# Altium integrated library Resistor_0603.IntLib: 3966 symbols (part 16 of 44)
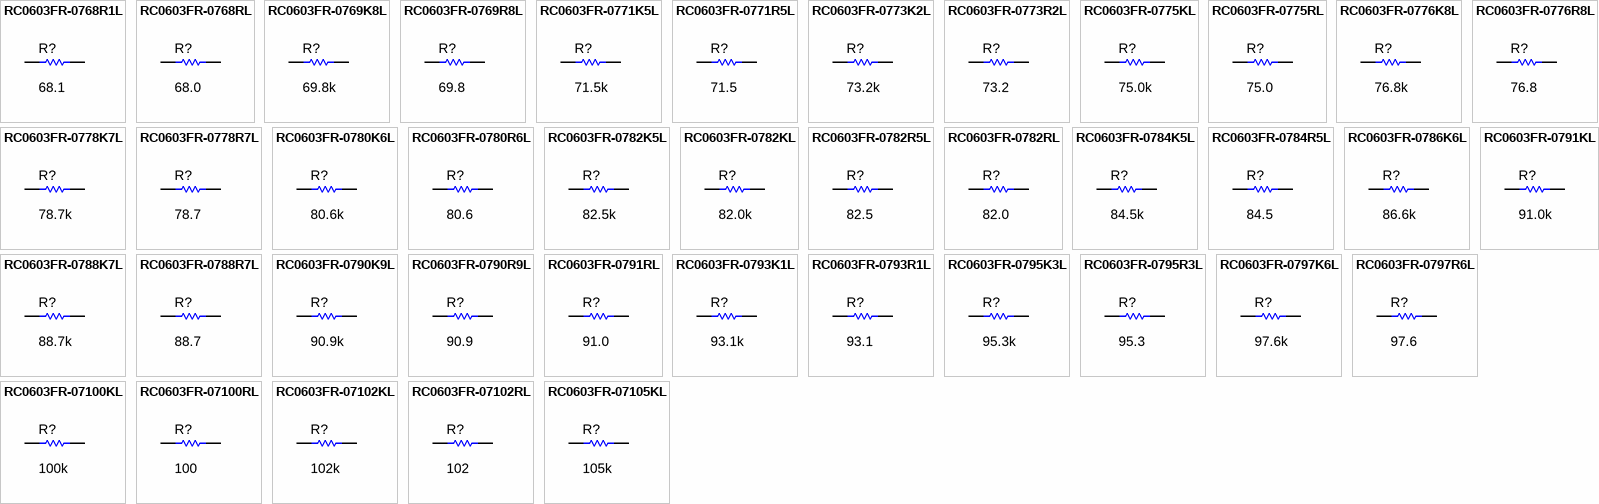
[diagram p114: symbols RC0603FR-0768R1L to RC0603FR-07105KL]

## RC0603FR-0790R9L
designator R?  ValueDisplayed: 90.9  (hidden comment: RC0603FR-0790R9L)
RES, 90.9, 1%, 0.1 W, 0603; Manufacturer: Yageo America; CompType: Resistor; Value: 90.9; Value_Code: 90R9; Tolerance_%: 1; Power_W: 0.1; Value2: 0.1W; VDC_V: 150; TempCo: 200 ppm/C; SizeArea_mm2: 1.28; SizeX_mm: 1.6; SizeY_mm: 0.8; EIA_Code: E96; U/M: EA; AEC Category: Q200
signal-integrity model Resistor
simulation model Resistor
footprint 0603
footprint 0603M
footprint 0603L
footprint 0603_HV
footprint 0603S
pins: 1, 2

## RC0603FR-0791KL
designator R?  ValueDisplayed: 91.0k  (hidden comment: RC0603FR-0791KL)
RES, 91.0 k, 1%, 0.1 W, 0603; Manufacturer: Yageo America; CompType: Resistor; Value: 91.0k; Res_ohm: 91000; Value_Code: 91k0; Tolerance_%: 1; Power_W: 0.1; Value2: 0.1W; VDC_V: 150; TempCo: 200 ppm/C; SizeArea_mm2: 1.28; SizeX_mm: 1.6; SizeY_mm: 0.8; U/M: EA; AEC Category: Q200
signal-integrity model Resistor
simulation model Resistor
footprint 0603
footprint 0603M
footprint 0603L
footprint 0603_HV
footprint 0603S
pins: 1, 2

## RC0603FR-0791RL
designator R?  ValueDisplayed: 91.0  (hidden comment: RC0603FR-0791RL)
RES, 91.0, 1%, 0.1 W, 0603; Manufacturer: Yageo America; CompType: Resistor; Value: 91.0; Res_ohm: 91; Value_Code: 91R0; Tolerance_%: 1; Power_W: 0.1; Value2: 0.1W; VDC_V: 150; TempCo: 200 ppm/C; SizeArea_mm2: 1.28; SizeX_mm: 1.6; SizeY_mm: 0.8; U/M: EA; AEC Category: Q200
signal-integrity model Resistor
simulation model Resistor
footprint 0603
footprint 0603M
footprint 0603L
footprint 0603_HV
footprint 0603S
pins: 1, 2

## RC0603FR-0793K1L
designator R?  ValueDisplayed: 93.1k  (hidden comment: RC0603FR-0793K1L)
RES, 93.1 k, 1%, 0.1 W, 0603; Manufacturer: Yageo America; CompType: Resistor; Value: 93.1k; Res_ohm: 93100; Value_Code: 93k1; Tolerance_%: 1; Power_W: 0.1; Value2: 0.1W; VDC_V: 150; TempCo: 200 ppm/C; SizeArea_mm2: 1.28; SizeX_mm: 1.6; SizeY_mm: 0.8; EIA_Code: E96; U/M: EA; AEC Category: Q200; Green_Lifecycle: Active; Green_REACh: Passed
signal-integrity model Resistor
simulation model Resistor
footprint 0603
footprint 0603M
footprint 0603L
footprint 0603_HV
footprint 0603S
pins: 1, 2

## RC0603FR-0793R1L
designator R?  ValueDisplayed: 93.1  (hidden comment: RC0603FR-0793R1L)
RES, 93.1, 1%, 0.1 W, 0603; Manufacturer: Yageo America; CompType: Resistor; Value: 93.1; Value_Code: 93R1; Tolerance_%: 1; Power_W: 0.1; Value2: 0.1W; VDC_V: 150; TempCo: 200 ppm/C; SizeArea_mm2: 1.28; SizeX_mm: 1.6; SizeY_mm: 0.8; EIA_Code: E96; U/M: EA; AEC Category: Q200
signal-integrity model Resistor
simulation model Resistor
footprint 0603
footprint 0603M
footprint 0603L
footprint 0603_HV
footprint 0603S
pins: 1, 2

## RC0603FR-0795K3L
designator R?  ValueDisplayed: 95.3k  (hidden comment: RC0603FR-0795K3L)
RES, 95.3 k, 1%, 0.1 W, 0603; Manufacturer: Yageo America; CompType: Resistor; Value: 95.3k; Res_ohm: 95300; Value_Code: 95k3; Tolerance_%: 1; Power_W: 0.1; Value2: 0.1W; VDC_V: 150; TempCo: 200 ppm/C; SizeArea_mm2: 1.28; SizeX_mm: 1.6; SizeY_mm: 0.8; EIA_Code: E96; U/M: EA; AEC Category: Q200; Green_Lifecycle: Active; Green_REACh: Passed
signal-integrity model Resistor
simulation model Resistor
footprint 0603
footprint 0603M
footprint 0603L
footprint 0603_HV
footprint 0603S
pins: 1, 2

## RC0603FR-0795R3L
designator R?  ValueDisplayed: 95.3  (hidden comment: RC0603FR-0795R3L)
RES, 95.3, 1%, 0.1 W, 0603; Manufacturer: Yageo America; CompType: Resistor; Value: 95.3; Value_Code: 95R3; Tolerance_%: 1; Power_W: 0.1; Value2: 0.1W; VDC_V: 150; TempCo: 200 ppm/C; SizeArea_mm2: 1.28; SizeX_mm: 1.6; SizeY_mm: 0.8; EIA_Code: E96; U/M: EA; AEC Category: Q200
signal-integrity model Resistor
simulation model Resistor
footprint 0603
footprint 0603M
footprint 0603L
footprint 0603_HV
footprint 0603S
pins: 1, 2

## RC0603FR-0797K6L
designator R?  ValueDisplayed: 97.6k  (hidden comment: RC0603FR-0797K6L)
RES, 97.6 k, 1%, 0.1 W, 0603; Manufacturer: Yageo America; CompType: Resistor; Value: 97.6k; Res_ohm: 97600; Value_Code: 97k6; Tolerance_%: 1; Power_W: 0.1; Value2: 0.1W; VDC_V: 150; TempCo: 200 ppm/C; SizeArea_mm2: 1.28; SizeX_mm: 1.6; SizeY_mm: 0.8; EIA_Code: E96; U/M: EA; AEC Category: Q200
signal-integrity model Resistor
simulation model Resistor
footprint 0603
footprint 0603M
footprint 0603L
footprint 0603_HV
footprint 0603S
pins: 1, 2

## RC0603FR-0797R6L
designator R?  ValueDisplayed: 97.6  (hidden comment: RC0603FR-0797R6L)
RES, 97.6, 1%, 0.1 W, 0603; Manufacturer: Yageo America; CompType: Resistor; Value: 97.6; Value_Code: 97R6; Tolerance_%: 1; Power_W: 0.1; Value2: 0.1W; VDC_V: 150; TempCo: 200 ppm/C; SizeArea_mm2: 1.28; SizeX_mm: 1.6; SizeY_mm: 0.8; EIA_Code: E96; U/M: EA; AEC Category: Q200
signal-integrity model Resistor
simulation model Resistor
footprint 0603
footprint 0603M
footprint 0603L
footprint 0603_HV
footprint 0603S
pins: 1, 2

## RC0603FR-07100KL
designator R?  ValueDisplayed: 100k  (hidden comment: RC0603FR-07100KL)
RES, 100 k, 1%, 0.1 W, 0603; Manufacturer: Yageo America; CompType: Resistor; Value: 100k; Res_ohm: 100000; Tolerance_%: 1; Power_W: 0.1; Value2: 0.1W; VDC_V: 150; TempCo: 200 ppm/C; SizeArea_mm2: 1.28; SizeX_mm: 1.6; SizeY_mm: 0.8; EIA_Code: E96; U/M: EA; AEC Category: Q200; Green_Lifecycle: Active; Green_REACh: Passed
signal-integrity model Resistor
simulation model Resistor
footprint 0603
footprint 0603M
footprint 0603L
footprint 0603_HV
footprint 0603S
pins: 1, 2

## RC0603FR-07100RL
designator R?  ValueDisplayed: 100  (hidden comment: RC0603FR-07100RL)
RES, 100, 1%, 0.1 W, 0603; Manufacturer: Yageo America; CompType: Resistor; Value: 100; Value_Code: 100R; Tolerance_%: 1; Power_W: 0.1; Value2: 0.1W; VDC_V: 150; TempCo: 200 ppm/C; SizeArea_mm2: 1.28; SizeX_mm: 1.6; SizeY_mm: 0.8; EIA_Code: E96; U/M: EA; AEC Category: Q200; Green_Lifecycle: Active; Green_REACh: Passed
signal-integrity model Resistor
simulation model Resistor
footprint 0603
footprint 0603M
footprint 0603L
footprint 0603_HV
footprint 0603S
pins: 1, 2

## RC0603FR-07102KL
designator R?  ValueDisplayed: 102k  (hidden comment: RC0603FR-07102KL)
RES, 102 k, 1%, 0.1 W, 0603; Manufacturer: Yageo America; CompType: Resistor; Value: 102k; Res_ohm: 102000; Tolerance_%: 1; Power_W: 0.1; Value2: 0.1W; VDC_V: 150; TempCo: 200 ppm/C; SizeArea_mm2: 1.28; SizeX_mm: 1.6; SizeY_mm: 0.8; EIA_Code: E96; U/M: EA; AEC Category: Q200; Green_Lifecycle: Active; Green_REACh: Passed
signal-integrity model Resistor
simulation model Resistor
footprint 0603
footprint 0603M
footprint 0603L
footprint 0603_HV
footprint 0603S
pins: 1, 2

## RC0603FR-07102RL
designator R?  ValueDisplayed: 102  (hidden comment: RC0603FR-07102RL)
RES, 102, 1%, 0.1 W, 0603; Manufacturer: Yageo America; CompType: Resistor; Value: 102; Value_Code: 102R; Tolerance_%: 1; Power_W: 0.1; Value2: 0.1W; VDC_V: 150; TempCo: 200 ppm/C; SizeArea_mm2: 1.28; SizeX_mm: 1.6; SizeY_mm: 0.8; EIA_Code: E96; U/M: EA; AEC Category: Q200
signal-integrity model Resistor
simulation model Resistor
footprint 0603
footprint 0603M
footprint 0603L
footprint 0603_HV
footprint 0603S
pins: 1, 2

## RC0603FR-07105KL
designator R?  ValueDisplayed: 105k  (hidden comment: RC0603FR-07105KL)
RES, 105 k, 1%, 0.1 W, 0603; Manufacturer: Yageo America; CompType: Resistor; Value: 105k; Res_ohm: 105000; Tolerance_%: 1; Power_W: 0.1; Value2: 0.1W; VDC_V: 150; TempCo: 200 ppm/C; SizeArea_mm2: 1.28; SizeX_mm: 1.6; SizeY_mm: 0.8; EIA_Code: E96; U/M: EA; AEC Category: Q200
signal-integrity model Resistor
simulation model Resistor
footprint 0603
footprint 0603M
footprint 0603L
footprint 0603_HV
footprint 0603S
pins: 1, 2

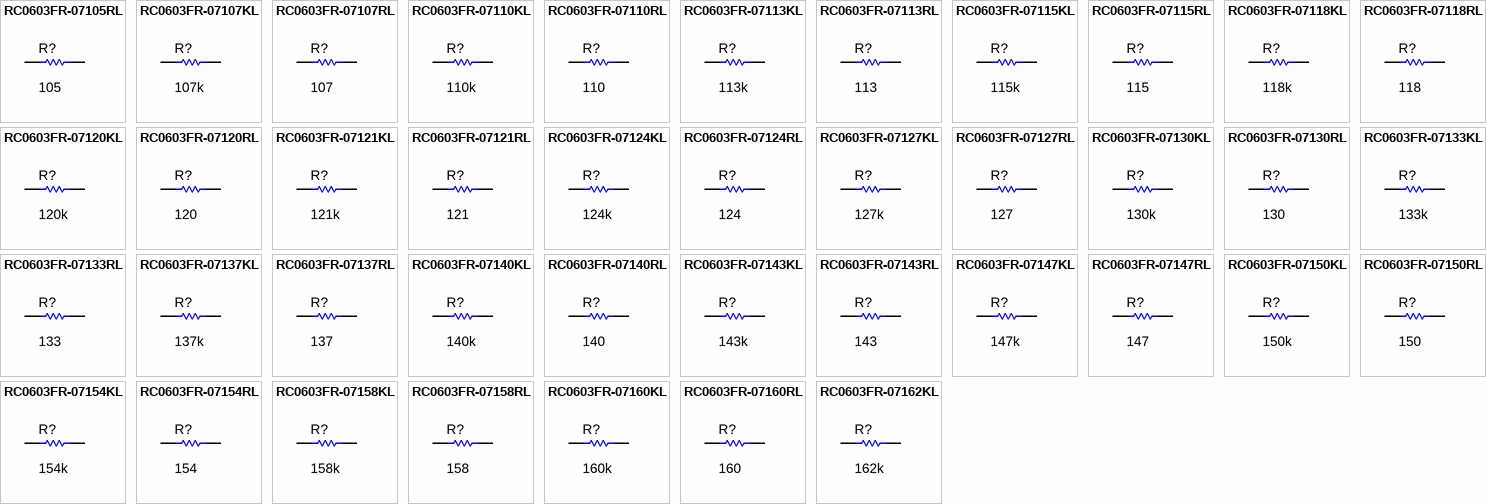
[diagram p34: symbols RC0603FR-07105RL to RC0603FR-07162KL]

## RC0603FR-07105RL
designator R?  ValueDisplayed: 105  (hidden comment: RC0603FR-07105RL)
RES, 105, 1%, 0.1 W, 0603; Manufacturer: Yageo America; CompType: Resistor; Value: 105; Value_Code: 105R; Tolerance_%: 1; Power_W: 0.1; Value2: 0.1W; VDC_V: 150; TempCo: 200 ppm/C; SizeArea_mm2: 1.28; SizeX_mm: 1.6; SizeY_mm: 0.8; EIA_Code: E96; U/M: EA; AEC Category: Q200
signal-integrity model Resistor
simulation model Resistor
footprint 0603
footprint 0603M
footprint 0603L
footprint 0603_HV
footprint 0603S
pins: 1, 2

## RC0603FR-07107KL
designator R?  ValueDisplayed: 107k  (hidden comment: RC0603FR-07107KL)
RES, 107 k, 1%, 0.1 W, 0603; Manufacturer: Yageo America; CompType: Resistor; Value: 107k; Res_ohm: 107000; Tolerance_%: 1; Power_W: 0.1; Value2: 0.1W; VDC_V: 150; TempCo: 200 ppm/C; SizeArea_mm2: 1.28; SizeX_mm: 1.6; SizeY_mm: 0.8; EIA_Code: E96; U/M: EA; AEC Category: Q200; Green_Lifecycle: Active; Green_REACh: Passed
signal-integrity model Resistor
simulation model Resistor
footprint 0603
footprint 0603M
footprint 0603L
footprint 0603_HV
footprint 0603S
pins: 1, 2

## RC0603FR-07107RL
designator R?  ValueDisplayed: 107  (hidden comment: RC0603FR-07107RL)
RES, 107, 1%, 0.1 W, 0603; Manufacturer: Yageo America; CompType: Resistor; Value: 107; Value_Code: 107R; Tolerance_%: 1; Power_W: 0.1; Value2: 0.1W; VDC_V: 150; TempCo: 200 ppm/C; SizeArea_mm2: 1.28; SizeX_mm: 1.6; SizeY_mm: 0.8; EIA_Code: E96; U/M: EA; AEC Category: Q200
signal-integrity model Resistor
simulation model Resistor
footprint 0603
footprint 0603M
footprint 0603L
footprint 0603_HV
footprint 0603S
pins: 1, 2

## RC0603FR-07110KL
designator R?  ValueDisplayed: 110k  (hidden comment: RC0603FR-07110KL)
RES, 110 k, 1%, 0.1 W, 0603; Manufacturer: Yageo America; CompType: Resistor; Value: 110k; Res_ohm: 110000; Tolerance_%: 1; Power_W: 0.1; Value2: 0.1W; VDC_V: 150; TempCo: 200 ppm/C; SizeArea_mm2: 1.28; SizeX_mm: 1.6; SizeY_mm: 0.8; EIA_Code: E96; U/M: EA; AEC Category: Q200
signal-integrity model Resistor
simulation model Resistor
footprint 0603
footprint 0603M
footprint 0603L
footprint 0603_HV
footprint 0603S
pins: 1, 2

## RC0603FR-07110RL
designator R?  ValueDisplayed: 110  (hidden comment: RC0603FR-07110RL)
RES, 110, 1%, 0.1 W, 0603; Manufacturer: Yageo America; CompType: Resistor; Value: 110; Value_Code: 110R; Tolerance_%: 1; Power_W: 0.1; Value2: 0.1W; VDC_V: 150; TempCo: 200 ppm/C; SizeArea_mm2: 1.28; SizeX_mm: 1.6; SizeY_mm: 0.8; EIA_Code: E96; U/M: EA; AEC Category: Q200
signal-integrity model Resistor
simulation model Resistor
footprint 0603
footprint 0603M
footprint 0603L
footprint 0603_HV
footprint 0603S
pins: 1, 2

## RC0603FR-07113KL
designator R?  ValueDisplayed: 113k  (hidden comment: RC0603FR-07113KL)
RES, 113 k, 1%, 0.1 W, 0603; Manufacturer: Yageo America; CompType: Resistor; Value: 113k; Res_ohm: 113000; Tolerance_%: 1; Power_W: 0.1; Value2: 0.1W; VDC_V: 150; TempCo: 200 ppm/C; SizeArea_mm2: 1.28; SizeX_mm: 1.6; SizeY_mm: 0.8; EIA_Code: E96; U/M: EA; AEC Category: Q200
signal-integrity model Resistor
simulation model Resistor
footprint 0603
footprint 0603M
footprint 0603L
footprint 0603_HV
footprint 0603S
pins: 1, 2

## RC0603FR-07113RL
designator R?  ValueDisplayed: 113  (hidden comment: RC0603FR-07113RL)
RES, 113, 1%, 0.1 W, 0603; Manufacturer: Yageo America; CompType: Resistor; Value: 113; Value_Code: 113R; Tolerance_%: 1; Power_W: 0.1; Value2: 0.1W; VDC_V: 150; TempCo: 200 ppm/C; SizeArea_mm2: 1.28; SizeX_mm: 1.6; SizeY_mm: 0.8; EIA_Code: E96; U/M: EA; AEC Category: Q200
signal-integrity model Resistor
simulation model Resistor
footprint 0603
footprint 0603M
footprint 0603L
footprint 0603_HV
footprint 0603S
pins: 1, 2

## RC0603FR-07115KL
designator R?  ValueDisplayed: 115k  (hidden comment: RC0603FR-07115KL)
RES, 115 k, 1%, 0.1 W, 0603; Manufacturer: Yageo America; CompType: Resistor; Value: 115k; Res_ohm: 115000; Tolerance_%: 1; Power_W: 0.1; Value2: 0.1W; VDC_V: 150; TempCo: 200 ppm/C; SizeArea_mm2: 1.28; SizeX_mm: 1.6; SizeY_mm: 0.8; EIA_Code: E96; U/M: EA; AEC Category: Q200
signal-integrity model Resistor
simulation model Resistor
footprint 0603
footprint 0603M
footprint 0603L
footprint 0603_HV
footprint 0603S
pins: 1, 2

## RC0603FR-07115RL
designator R?  ValueDisplayed: 115  (hidden comment: RC0603FR-07115RL)
RES, 115, 1%, 0.1 W, 0603; Manufacturer: Yageo America; CompType: Resistor; Value: 115; Value_Code: 115R; Tolerance_%: 1; Power_W: 0.1; Value2: 0.1W; VDC_V: 150; TempCo: 200 ppm/C; SizeArea_mm2: 1.28; SizeX_mm: 1.6; SizeY_mm: 0.8; EIA_Code: E96; U/M: EA; AEC Category: Q200
signal-integrity model Resistor
simulation model Resistor
footprint 0603
footprint 0603M
footprint 0603L
footprint 0603_HV
footprint 0603S
pins: 1, 2

## RC0603FR-07118KL
designator R?  ValueDisplayed: 118k  (hidden comment: RC0603FR-07118KL)
RES, 118 k, 1%, 0.1 W, 0603; Manufacturer: Yageo America; CompType: Resistor; Value: 118k; Res_ohm: 118000; Tolerance_%: 1; Power_W: 0.1; Value2: 0.1W; VDC_V: 150; TempCo: 200 ppm/C; SizeArea_mm2: 1.28; SizeX_mm: 1.6; SizeY_mm: 0.8; EIA_Code: E96; U/M: EA; AEC Category: Q200; Green_Lifecycle: Active; Green_REACh: Passed
signal-integrity model Resistor
simulation model Resistor
footprint 0603
footprint 0603M
footprint 0603L
footprint 0603_HV
footprint 0603S
pins: 1, 2

## RC0603FR-07118RL
designator R?  ValueDisplayed: 118  (hidden comment: RC0603FR-07118RL)
RES, 118, 1%, 0.1 W, 0603; Manufacturer: Yageo America; CompType: Resistor; Value: 118; Value_Code: 118R; Tolerance_%: 1; Power_W: 0.1; Value2: 0.1W; VDC_V: 150; TempCo: 200 ppm/C; SizeArea_mm2: 1.28; SizeX_mm: 1.6; SizeY_mm: 0.8; EIA_Code: E96; U/M: EA; AEC Category: Q200
signal-integrity model Resistor
simulation model Resistor
footprint 0603
footprint 0603M
footprint 0603L
footprint 0603_HV
footprint 0603S
pins: 1, 2

## RC0603FR-07120KL
designator R?  ValueDisplayed: 120k  (hidden comment: RC0603FR-07120KL)
RES, 120 k, 1%, 0.1 W, 0603; Manufacturer: Yageo America; CompType: Resistor; Value: 120k; Res_ohm: 120000; Tolerance_%: 1; Power_W: 0.1; Value2: 0.1W; VDC_V: 150; TempCo: 200 ppm/C; SizeArea_mm2: 1.28; SizeX_mm: 1.6; SizeY_mm: 0.8; U/M: EA; AEC Category: Q200
signal-integrity model Resistor
simulation model Resistor
footprint 0603
footprint 0603M
footprint 0603L
footprint 0603_HV
footprint 0603S
pins: 1, 2

## RC0603FR-07120RL
designator R?  ValueDisplayed: 120  (hidden comment: RC0603FR-07120RL)
RES, 120, 1%, 0.1 W, 0603; Manufacturer: Yageo America; CompType: Resistor; Value: 120; Value_Code: 120R; Tolerance_%: 1; Power_W: 0.1; Value2: 0.1W; VDC_V: 150; TempCo: 200 ppm/C; SizeArea_mm2: 1.28; SizeX_mm: 1.6; SizeY_mm: 0.8; U/M: EA; AEC Category: Q200; Green_Lifecycle: Active; Green_REACh: Passed
signal-integrity model Resistor
simulation model Resistor
footprint 0603
footprint 0603M
footprint 0603L
footprint 0603_HV
footprint 0603S
pins: 1, 2

## RC0603FR-07121KL
designator R?  ValueDisplayed: 121k  (hidden comment: RC0603FR-07121KL)
RES, 121 k, 1%, 0.1 W, 0603; Manufacturer: Yageo America; CompType: Resistor; Value: 121k; Res_ohm: 121000; Tolerance_%: 1; Power_W: 0.1; Value2: 0.1W; VDC_V: 150; TempCo: 200 ppm/C; SizeArea_mm2: 1.28; SizeX_mm: 1.6; SizeY_mm: 0.8; EIA_Code: E96; U/M: EA; AEC Category: Q200; Green_Lifecycle: Active; Green_REACh: Passed
signal-integrity model Resistor
simulation model Resistor
footprint 0603
footprint 0603M
footprint 0603L
footprint 0603_HV
footprint 0603S
pins: 1, 2

## RC0603FR-07121RL
designator R?  ValueDisplayed: 121  (hidden comment: RC0603FR-07121RL)
RES, 121, 1%, 0.1 W, 0603; Manufacturer: Yageo America; CompType: Resistor; Value: 121; Value_Code: 121R; Tolerance_%: 1; Power_W: 0.1; Value2: 0.1W; VDC_V: 150; TempCo: 200 ppm/C; SizeArea_mm2: 1.28; SizeX_mm: 1.6; SizeY_mm: 0.8; EIA_Code: E96; U/M: EA; AEC Category: Q200
signal-integrity model Resistor
simulation model Resistor
footprint 0603
footprint 0603M
footprint 0603L
footprint 0603_HV
footprint 0603S
pins: 1, 2

## RC0603FR-07124KL
designator R?  ValueDisplayed: 124k  (hidden comment: RC0603FR-07124KL)
RES, 124 k, 1%, 0.1 W, 0603; Manufacturer: Yageo America; CompType: Resistor; Value: 124k; Res_ohm: 124000; Tolerance_%: 1; Power_W: 0.1; Value2: 0.1W; VDC_V: 150; TempCo: 200 ppm/C; SizeArea_mm2: 1.28; SizeX_mm: 1.6; SizeY_mm: 0.8; EIA_Code: E96; U/M: EA; AEC Category: Q200; Green_Lifecycle: Active; Green_REACh: Passed
signal-integrity model Resistor
simulation model Resistor
footprint 0603
footprint 0603M
footprint 0603L
footprint 0603_HV
footprint 0603S
pins: 1, 2

## RC0603FR-07124RL
designator R?  ValueDisplayed: 124  (hidden comment: RC0603FR-07124RL)
RES, 124, 1%, 0.1 W, 0603; Manufacturer: Yageo America; CompType: Resistor; Value: 124; Value_Code: 124R; Tolerance_%: 1; Power_W: 0.1; Value2: 0.1W; VDC_V: 150; TempCo: 200 ppm/C; SizeArea_mm2: 1.28; SizeX_mm: 1.6; SizeY_mm: 0.8; EIA_Code: E96; U/M: EA; AEC Category: Q200
signal-integrity model Resistor
simulation model Resistor
footprint 0603
footprint 0603M
footprint 0603L
footprint 0603_HV
footprint 0603S
pins: 1, 2

## RC0603FR-07127KL
designator R?  ValueDisplayed: 127k  (hidden comment: RC0603FR-07127KL)
RES, 127 k, 1%, 0.1 W, 0603; Manufacturer: Yageo America; CompType: Resistor; Value: 127k; Res_ohm: 127000; Tolerance_%: 1; Power_W: 0.1; Value2: 0.1W; VDC_V: 150; TempCo: 200 ppm/C; SizeArea_mm2: 1.28; SizeX_mm: 1.6; SizeY_mm: 0.8; EIA_Code: E96; U/M: EA; AEC Category: Q200; Green_Lifecycle: Active; Green_REACh: Passed
signal-integrity model Resistor
simulation model Resistor
footprint 0603
footprint 0603M
footprint 0603L
footprint 0603_HV
footprint 0603S
pins: 1, 2

## RC0603FR-07127RL
designator R?  ValueDisplayed: 127  (hidden comment: RC0603FR-07127RL)
RES, 127, 1%, 0.1 W, 0603; Manufacturer: Yageo America; CompType: Resistor; Value: 127; Value_Code: 127R; Tolerance_%: 1; Power_W: 0.1; Value2: 0.1W; VDC_V: 150; TempCo: 200 ppm/C; SizeArea_mm2: 1.28; SizeX_mm: 1.6; SizeY_mm: 0.8; EIA_Code: E96; U/M: EA; AEC Category: Q200
signal-integrity model Resistor
simulation model Resistor
footprint 0603
footprint 0603M
footprint 0603L
footprint 0603_HV
footprint 0603S
pins: 1, 2

## RC0603FR-07130KL
designator R?  ValueDisplayed: 130k  (hidden comment: RC0603FR-07130KL)
RES, 130 k, 1%, 0.1 W, 0603; Manufacturer: Yageo America; CompType: Resistor; Value: 130k; Res_ohm: 130000; Tolerance_%: 1; Power_W: 0.1; Value2: 0.1W; VDC_V: 150; TempCo: 200 ppm/C; SizeArea_mm2: 1.28; SizeX_mm: 1.6; SizeY_mm: 0.8; EIA_Code: E96; U/M: EA; AEC Category: Q200
signal-integrity model Resistor
simulation model Resistor
footprint 0603
footprint 0603M
footprint 0603L
footprint 0603_HV
footprint 0603S
pins: 1, 2

## RC0603FR-07130RL
designator R?  ValueDisplayed: 130  (hidden comment: RC0603FR-07130RL)
RES, 130, 1%, 0.1 W, 0603; Manufacturer: Yageo America; CompType: Resistor; Value: 130; Value_Code: 130R; Tolerance_%: 1; Power_W: 0.1; Value2: 0.1W; VDC_V: 150; TempCo: 200 ppm/C; SizeArea_mm2: 1.28; SizeX_mm: 1.6; SizeY_mm: 0.8; EIA_Code: E96; U/M: EA; AEC Category: Q200; Green_Lifecycle: Active; Green_REACh: Passed
signal-integrity model Resistor
simulation model Resistor
footprint 0603
footprint 0603M
footprint 0603L
footprint 0603_HV
footprint 0603S
pins: 1, 2

## RC0603FR-07133KL
designator R?  ValueDisplayed: 133k  (hidden comment: RC0603FR-07133KL)
RES, 133 k, 1%, 0.1 W, 0603; Manufacturer: Yageo America; CompType: Resistor; Value: 133k; Res_ohm: 133000; Tolerance_%: 1; Power_W: 0.1; Value2: 0.1W; VDC_V: 150; TempCo: 200 ppm/C; SizeArea_mm2: 1.28; SizeX_mm: 1.6; SizeY_mm: 0.8; EIA_Code: E96; U/M: EA; AEC Category: Q200; Green_Lifecycle: Active; Green_REACh: Passed
signal-integrity model Resistor
simulation model Resistor
footprint 0603
footprint 0603M
footprint 0603L
footprint 0603_HV
footprint 0603S
pins: 1, 2

## RC0603FR-07133RL
designator R?  ValueDisplayed: 133  (hidden comment: RC0603FR-07133RL)
RES, 133, 1%, 0.1 W, 0603; Manufacturer: Yageo America; CompType: Resistor; Value: 133; Value_Code: 133R; Tolerance_%: 1; Power_W: 0.1; Value2: 0.1W; VDC_V: 150; TempCo: 200 ppm/C; SizeArea_mm2: 1.28; SizeX_mm: 1.6; SizeY_mm: 0.8; EIA_Code: E96; U/M: EA; AEC Category: Q200
signal-integrity model Resistor
simulation model Resistor
footprint 0603
footprint 0603M
footprint 0603L
footprint 0603_HV
footprint 0603S
pins: 1, 2

## RC0603FR-07137KL
designator R?  ValueDisplayed: 137k  (hidden comment: RC0603FR-07137KL)
RES, 137 k, 1%, 0.1 W, 0603; Manufacturer: Yageo America; CompType: Resistor; Value: 137k; Res_ohm: 137000; Tolerance_%: 1; Power_W: 0.1; Value2: 0.1W; VDC_V: 150; TempCo: 200 ppm/C; SizeArea_mm2: 1.28; SizeX_mm: 1.6; SizeY_mm: 0.8; EIA_Code: E96; U/M: EA; AEC Category: Q200
signal-integrity model Resistor
simulation model Resistor
footprint 0603
footprint 0603M
footprint 0603L
footprint 0603_HV
footprint 0603S
pins: 1, 2

## RC0603FR-07137RL
designator R?  ValueDisplayed: 137  (hidden comment: RC0603FR-07137RL)
RES, 137, 1%, 0.1 W, 0603; Manufacturer: Yageo America; CompType: Resistor; Value: 137; Value_Code: 137R; Tolerance_%: 1; Power_W: 0.1; Value2: 0.1W; VDC_V: 150; TempCo: 200 ppm/C; SizeArea_mm2: 1.28; SizeX_mm: 1.6; SizeY_mm: 0.8; EIA_Code: E96; U/M: EA; AEC Category: Q200
signal-integrity model Resistor
simulation model Resistor
footprint 0603
footprint 0603M
footprint 0603L
footprint 0603_HV
footprint 0603S
pins: 1, 2

## RC0603FR-07140KL
designator R?  ValueDisplayed: 140k  (hidden comment: RC0603FR-07140KL)
RES, 140 k, 1%, 0.1 W, 0603; Manufacturer: Yageo America; CompType: Resistor; Value: 140k; Res_ohm: 140000; Tolerance_%: 1; Power_W: 0.1; Value2: 0.1W; VDC_V: 150; TempCo: 200 ppm/C; SizeArea_mm2: 1.28; SizeX_mm: 1.6; SizeY_mm: 0.8; EIA_Code: E96; U/M: EA; AEC Category: Q200
signal-integrity model Resistor
simulation model Resistor
footprint 0603
footprint 0603M
footprint 0603L
footprint 0603_HV
footprint 0603S
pins: 1, 2

## RC0603FR-07140RL
designator R?  ValueDisplayed: 140  (hidden comment: RC0603FR-07140RL)
RES, 140, 1%, 0.1 W, 0603; Manufacturer: Yageo America; CompType: Resistor; Value: 140; Value_Code: 140R; Tolerance_%: 1; Power_W: 0.1; Value2: 0.1W; VDC_V: 150; TempCo: 200 ppm/C; SizeArea_mm2: 1.28; SizeX_mm: 1.6; SizeY_mm: 0.8; EIA_Code: E96; U/M: EA; AEC Category: Q200
signal-integrity model Resistor
simulation model Resistor
footprint 0603
footprint 0603M
footprint 0603L
footprint 0603_HV
footprint 0603S
pins: 1, 2

## RC0603FR-07143KL
designator R?  ValueDisplayed: 143k  (hidden comment: RC0603FR-07143KL)
RES, 143 k, 1%, 0.1 W, 0603; Manufacturer: Yageo America; CompType: Resistor; Value: 143k; Res_ohm: 143000; Tolerance_%: 1; Power_W: 0.1; Value2: 0.1W; VDC_V: 150; TempCo: 200 ppm/C; SizeArea_mm2: 1.28; SizeX_mm: 1.6; SizeY_mm: 0.8; EIA_Code: E96; U/M: EA; AEC Category: Q200; Green_Lifecycle: Active; Green_REACh: Passed
signal-integrity model Resistor
simulation model Resistor
footprint 0603
footprint 0603M
footprint 0603L
footprint 0603_HV
footprint 0603S
pins: 1, 2

## RC0603FR-07143RL
designator R?  ValueDisplayed: 143  (hidden comment: RC0603FR-07143RL)
RES, 143, 1%, 0.1 W, 0603; Manufacturer: Yageo America; CompType: Resistor; Value: 143; Value_Code: 143R; Tolerance_%: 1; Power_W: 0.1; Value2: 0.1W; VDC_V: 150; TempCo: 200 ppm/C; SizeArea_mm2: 1.28; SizeX_mm: 1.6; SizeY_mm: 0.8; EIA_Code: E96; U/M: EA; AEC Category: Q200
signal-integrity model Resistor
simulation model Resistor
footprint 0603
footprint 0603M
footprint 0603L
footprint 0603_HV
footprint 0603S
pins: 1, 2

## RC0603FR-07147KL
designator R?  ValueDisplayed: 147k  (hidden comment: RC0603FR-07147KL)
RES, 147 k, 1%, 0.1 W, 0603; Manufacturer: Yageo America; CompType: Resistor; Value: 147k; Res_ohm: 147000; Tolerance_%: 1; Power_W: 0.1; Value2: 0.1W; VDC_V: 150; TempCo: 200 ppm/C; SizeArea_mm2: 1.28; SizeX_mm: 1.6; SizeY_mm: 0.8; EIA_Code: E96; U/M: EA; AEC Category: Q200; Green_Lifecycle: Active; Green_REACh: Passed
signal-integrity model Resistor
simulation model Resistor
footprint 0603
footprint 0603M
footprint 0603L
footprint 0603_HV
footprint 0603S
pins: 1, 2

## RC0603FR-07147RL
designator R?  ValueDisplayed: 147  (hidden comment: RC0603FR-07147RL)
RES, 147, 1%, 0.1 W, 0603; Manufacturer: Yageo America; CompType: Resistor; Value: 147; Value_Code: 147R; Tolerance_%: 1; Power_W: 0.1; Value2: 0.1W; VDC_V: 150; TempCo: 200 ppm/C; SizeArea_mm2: 1.28; SizeX_mm: 1.6; SizeY_mm: 0.8; EIA_Code: E96; U/M: EA; AEC Category: Q200
signal-integrity model Resistor
simulation model Resistor
footprint 0603
footprint 0603M
footprint 0603L
footprint 0603_HV
footprint 0603S
pins: 1, 2

## RC0603FR-07150KL
designator R?  ValueDisplayed: 150k  (hidden comment: RC0603FR-07150KL)
RES, 150 k, 1%, 0.1 W, 0603; Manufacturer: Yageo America; CompType: Resistor; Value: 150k; Res_ohm: 150000; Tolerance_%: 1; Power_W: 0.1; Value2: 0.1W; VDC_V: 150; TempCo: 200 ppm/C; SizeArea_mm2: 1.28; SizeX_mm: 1.6; SizeY_mm: 0.8; EIA_Code: E96; U/M: EA; AEC Category: Q200; Green_Lifecycle: Active; Green_REACh: Passed
signal-integrity model Resistor
simulation model Resistor
footprint 0603
footprint 0603M
footprint 0603L
footprint 0603_HV
footprint 0603S
pins: 1, 2

## RC0603FR-07150RL
designator R?  ValueDisplayed: 150  (hidden comment: RC0603FR-07150RL)
RES, 150, 1%, 0.1 W, 0603; Manufacturer: Yageo America; CompType: Resistor; Value: 150; Value_Code: 150R; Tolerance_%: 1; Power_W: 0.1; Value2: 0.1W; TempCo: 200 ppm/C; SizeArea_mm2: 1.28; SizeX_mm: 1.6; SizeY_mm: 0.8; EIA_Code: E96; U/M: EA; AEC Category: Q200; Green_Lifecycle: Active; Green_REACh: Passed
signal-integrity model Resistor
simulation model Resistor
footprint 0603
footprint 0603M
footprint 0603L
footprint 0603_HV
footprint 0603S
pins: 1, 2

## RC0603FR-07154KL
designator R?  ValueDisplayed: 154k  (hidden comment: RC0603FR-07154KL)
RES, 154 k, 1%, 0.1 W, 0603; Manufacturer: Yageo America; CompType: Resistor; Value: 154k; Res_ohm: 154000; Tolerance_%: 1; Power_W: 0.1; Value2: 0.1W; VDC_V: 150; TempCo: 200 ppm/C; SizeArea_mm2: 1.28; SizeX_mm: 1.6; SizeY_mm: 0.8; EIA_Code: E96; U/M: EA; AEC Category: Q200
signal-integrity model Resistor
simulation model Resistor
footprint 0603
footprint 0603M
footprint 0603L
footprint 0603_HV
footprint 0603S
pins: 1, 2

## RC0603FR-07154RL
designator R?  ValueDisplayed: 154  (hidden comment: RC0603FR-07154RL)
RES, 154, 1%, 0.1 W, 0603; Manufacturer: Yageo America; CompType: Resistor; Value: 154; Value_Code: 154R; Tolerance_%: 1; Power_W: 0.1; Value2: 0.1W; VDC_V: 150; TempCo: 200 ppm/C; SizeArea_mm2: 1.28; SizeX_mm: 1.6; SizeY_mm: 0.8; EIA_Code: E96; U/M: EA; AEC Category: Q200
signal-integrity model Resistor
simulation model Resistor
footprint 0603
footprint 0603M
footprint 0603L
footprint 0603_HV
footprint 0603S
pins: 1, 2

## RC0603FR-07158KL
designator R?  ValueDisplayed: 158k  (hidden comment: RC0603FR-07158KL)
RES, 158 k, 1%, 0.1 W, 0603; Manufacturer: Yageo America; CompType: Resistor; Value: 158k; Res_ohm: 158000; Tolerance_%: 1; Power_W: 0.1; Value2: 0.1W; VDC_V: 150; TempCo: 200 ppm/C; SizeArea_mm2: 1.28; SizeX_mm: 1.6; SizeY_mm: 0.8; EIA_Code: E96; U/M: EA; AEC Category: Q200; Green_Lifecycle: Active; Green_REACh: Passed
signal-integrity model Resistor
simulation model Resistor
footprint 0603
footprint 0603M
footprint 0603L
footprint 0603_HV
footprint 0603S
pins: 1, 2

## RC0603FR-07158RL
designator R?  ValueDisplayed: 158  (hidden comment: RC0603FR-07158RL)
RES, 158, 1%, 0.1 W, 0603; Manufacturer: Yageo America; CompType: Resistor; Value: 158; Value_Code: 158R; Tolerance_%: 1; Power_W: 0.1; Value2: 0.1W; VDC_V: 150; TempCo: 200 ppm/C; SizeArea_mm2: 1.28; SizeX_mm: 1.6; SizeY_mm: 0.8; EIA_Code: E96; U/M: EA; AEC Category: Q200
signal-integrity model Resistor
simulation model Resistor
footprint 0603
footprint 0603M
footprint 0603L
footprint 0603_HV
footprint 0603S
pins: 1, 2

## RC0603FR-07160KL
designator R?  ValueDisplayed: 160k  (hidden comment: RC0603FR-07160KL)
RES, 160 k, 1%, 0.1 W, 0603; Manufacturer: Yageo America; CompType: Resistor; Value: 160k; Res_ohm: 160000; Tolerance_%: 1; Power_W: 0.1; Value2: 0.1W; VDC_V: 150; TempCo: 200 ppm/C; SizeArea_mm2: 1.28; SizeX_mm: 1.6; SizeY_mm: 0.8; U/M: EA; AEC Category: Q200; Green_Lifecycle: Active; Green_REACh: Passed
signal-integrity model Resistor
simulation model Resistor
footprint 0603
footprint 0603M
footprint 0603L
footprint 0603_HV
footprint 0603S
pins: 1, 2

## RC0603FR-07160RL
designator R?  ValueDisplayed: 160  (hidden comment: RC0603FR-07160RL)
RES, 160, 1%, 0.1 W, 0603; Manufacturer: Yageo America; CompType: Resistor; Value: 160; Value_Code: 160R; Tolerance_%: 1; Power_W: 0.1; Value2: 0.1W; VDC_V: 150; TempCo: 200 ppm/C; SizeArea_mm2: 1.28; SizeX_mm: 1.6; SizeY_mm: 0.8; U/M: EA; AEC Category: Q200
signal-integrity model Resistor
simulation model Resistor
footprint 0603
footprint 0603M
footprint 0603L
footprint 0603_HV
footprint 0603S
pins: 1, 2

## RC0603FR-07162KL
designator R?  ValueDisplayed: 162k  (hidden comment: RC0603FR-07162KL)
RES, 162 k, 1%, 0.1 W, 0603; Manufacturer: Yageo America; CompType: Resistor; Value: 162k; Res_ohm: 162000; Tolerance_%: 1; Power_W: 0.1; Value2: 0.1W; VDC_V: 150; TempCo: 200 ppm/C; SizeArea_mm2: 1.28; SizeX_mm: 1.6; SizeY_mm: 0.8; EIA_Code: E96; U/M: EA; AEC Category: Q200; Green_Lifecycle: Active; Green_REACh: Passed
signal-integrity model Resistor
simulation model Resistor
footprint 0603
footprint 0603M
footprint 0603L
footprint 0603_HV
footprint 0603S
pins: 1, 2

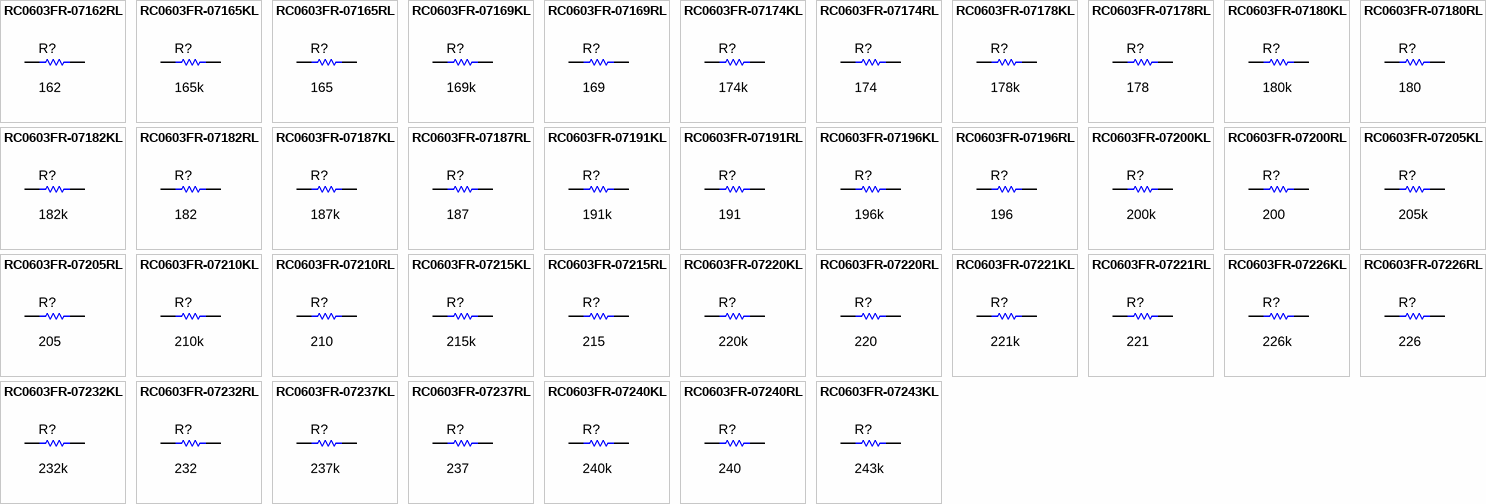
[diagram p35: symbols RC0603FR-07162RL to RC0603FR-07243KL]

## RC0603FR-07162RL
designator R?  ValueDisplayed: 162  (hidden comment: RC0603FR-07162RL)
RES, 162, 1%, 0.1 W, 0603; Manufacturer: Yageo America; CompType: Resistor; Value: 162; Value_Code: 162R; Tolerance_%: 1; Power_W: 0.1; Value2: 0.1W; VDC_V: 150; TempCo: 200 ppm/C; SizeArea_mm2: 1.28; SizeX_mm: 1.6; SizeY_mm: 0.8; EIA_Code: E96; U/M: EA; AEC Category: Q200
signal-integrity model Resistor
simulation model Resistor
footprint 0603
footprint 0603M
footprint 0603L
footprint 0603_HV
footprint 0603S
pins: 1, 2

## RC0603FR-07165KL
designator R?  ValueDisplayed: 165k  (hidden comment: RC0603FR-07165KL)
RES, 165 k, 1%, 0.1 W, 0603; Manufacturer: Yageo America; CompType: Resistor; Value: 165k; Res_ohm: 165000; Tolerance_%: 1; Power_W: 0.1; Value2: 0.1W; VDC_V: 150; TempCo: 200 ppm/C; SizeArea_mm2: 1.28; SizeX_mm: 1.6; SizeY_mm: 0.8; EIA_Code: E96; U/M: EA; AEC Category: Q200; Green_Lifecycle: Active; Green_REACh: Passed
signal-integrity model Resistor
simulation model Resistor
footprint 0603
footprint 0603M
footprint 0603L
footprint 0603_HV
footprint 0603S
pins: 1, 2

## RC0603FR-07165RL
designator R?  ValueDisplayed: 165  (hidden comment: RC0603FR-07165RL)
RES, 165, 1%, 0.1 W, 0603; Manufacturer: Yageo America; CompType: Resistor; Value: 165; Value_Code: 165R; Tolerance_%: 1; Power_W: 0.1; Value2: 0.1W; VDC_V: 150; TempCo: 200 ppm/C; SizeArea_mm2: 1.28; SizeX_mm: 1.6; SizeY_mm: 0.8; EIA_Code: E96; U/M: EA; AEC Category: Q200
signal-integrity model Resistor
simulation model Resistor
footprint 0603
footprint 0603M
footprint 0603L
footprint 0603_HV
footprint 0603S
pins: 1, 2

## RC0603FR-07169KL
designator R?  ValueDisplayed: 169k  (hidden comment: RC0603FR-07169KL)
RES, 169 k, 1%, 0.1 W, 0603; Manufacturer: Yageo America; CompType: Resistor; Value: 169k; Res_ohm: 169000; Tolerance_%: 1; Power_W: 0.1; Value2: 0.1W; VDC_V: 150; TempCo: 200 ppm/C; SizeArea_mm2: 1.28; SizeX_mm: 1.6; SizeY_mm: 0.8; EIA_Code: E96; U/M: EA; AEC Category: Q200; Green_Lifecycle: Active; Green_REACh: Passed
signal-integrity model Resistor
simulation model Resistor
footprint 0603
footprint 0603M
footprint 0603L
footprint 0603_HV
footprint 0603S
pins: 1, 2

## RC0603FR-07169RL
designator R?  ValueDisplayed: 169  (hidden comment: RC0603FR-07169RL)
RES, 169, 1%, 0.1 W, 0603; Manufacturer: Yageo America; CompType: Resistor; Value: 169; Value_Code: 169R; Tolerance_%: 1; Power_W: 0.1; Value2: 0.1W; VDC_V: 150; TempCo: 200 ppm/C; SizeArea_mm2: 1.28; SizeX_mm: 1.6; SizeY_mm: 0.8; EIA_Code: E96; U/M: EA; AEC Category: Q200
signal-integrity model Resistor
simulation model Resistor
footprint 0603
footprint 0603M
footprint 0603L
footprint 0603_HV
footprint 0603S
pins: 1, 2

## RC0603FR-07174KL
designator R?  ValueDisplayed: 174k  (hidden comment: RC0603FR-07174KL)
RES, 174 k, 1%, 0.1 W, 0603; Manufacturer: Yageo America; CompType: Resistor; Value: 174k; Res_ohm: 174000; Tolerance_%: 1; Power_W: 0.1; Value2: 0.1W; VDC_V: 150; TempCo: 200 ppm/C; SizeArea_mm2: 1.28; SizeX_mm: 1.6; SizeY_mm: 0.8; EIA_Code: E96; U/M: EA; AEC Category: Q200; Green_Lifecycle: Active; Green_REACh: Passed
signal-integrity model Resistor
simulation model Resistor
footprint 0603
footprint 0603M
footprint 0603L
footprint 0603_HV
footprint 0603S
pins: 1, 2

## RC0603FR-07174RL
designator R?  ValueDisplayed: 174  (hidden comment: RC0603FR-07174RL)
RES, 174, 1%, 0.1 W, 0603; Manufacturer: Yageo America; CompType: Resistor; Value: 174; Value_Code: 174R; Tolerance_%: 1; Power_W: 0.1; Value2: 0.1W; VDC_V: 150; TempCo: 200 ppm/C; SizeArea_mm2: 1.28; SizeX_mm: 1.6; SizeY_mm: 0.8; EIA_Code: E96; U/M: EA; AEC Category: Q200
signal-integrity model Resistor
simulation model Resistor
footprint 0603
footprint 0603M
footprint 0603L
footprint 0603_HV
footprint 0603S
pins: 1, 2

## RC0603FR-07178KL
designator R?  ValueDisplayed: 178k  (hidden comment: RC0603FR-07178KL)
RES, 178 k, 1%, 0.1 W, 0603; Manufacturer: Yageo America; CompType: Resistor; Value: 178k; Res_ohm: 178000; Tolerance_%: 1; Power_W: 0.1; Value2: 0.1W; VDC_V: 150; TempCo: 200 ppm/C; SizeArea_mm2: 1.28; SizeX_mm: 1.6; SizeY_mm: 0.8; EIA_Code: E96; U/M: EA; AEC Category: Q200; Green_Lifecycle: Active; Green_REACh: Passed
signal-integrity model Resistor
simulation model Resistor
footprint 0603
footprint 0603M
footprint 0603L
footprint 0603_HV
footprint 0603S
pins: 1, 2

## RC0603FR-07178RL
designator R?  ValueDisplayed: 178  (hidden comment: RC0603FR-07178RL)
RES, 178, 1%, 0.1 W, 0603; Manufacturer: Yageo America; CompType: Resistor; Value: 178; Value_Code: 178R; Tolerance_%: 1; Power_W: 0.1; Value2: 0.1W; VDC_V: 150; TempCo: 200 ppm/C; SizeArea_mm2: 1.28; SizeX_mm: 1.6; SizeY_mm: 0.8; EIA_Code: E96; U/M: EA; AEC Category: Q200
signal-integrity model Resistor
simulation model Resistor
footprint 0603
footprint 0603M
footprint 0603L
footprint 0603_HV
footprint 0603S
pins: 1, 2

## RC0603FR-07180KL
designator R?  ValueDisplayed: 180k  (hidden comment: RC0603FR-07180KL)
RES, 180 k, 1%, 0.1 W, 0603; Manufacturer: Yageo America; CompType: Resistor; Value: 180k; Res_ohm: 180000; Tolerance_%: 1; Power_W: 0.1; Value2: 0.1W; VDC_V: 150; TempCo: 200 ppm/C; SizeArea_mm2: 1.28; SizeX_mm: 1.6; SizeY_mm: 0.8; U/M: EA; AEC Category: Q200; Green_Lifecycle: Active; Green_REACh: Passed
signal-integrity model Resistor
simulation model Resistor
footprint 0603
footprint 0603M
footprint 0603L
footprint 0603_HV
footprint 0603S
pins: 1, 2

## RC0603FR-07180RL
designator R?  ValueDisplayed: 180  (hidden comment: RC0603FR-07180RL)
RES, 180, 1%, 0.1 W, 0603; Manufacturer: Yageo America; CompType: Resistor; Value: 180; Value_Code: 180R; Tolerance_%: 1; Power_W: 0.1; Value2: 0.1W; VDC_V: 150; TempCo: 200 ppm/C; SizeArea_mm2: 1.28; SizeX_mm: 1.6; SizeY_mm: 0.8; U/M: EA; AEC Category: Q200; Green_Lifecycle: Active; Green_REACh: Passed
signal-integrity model Resistor
simulation model Resistor
footprint 0603
footprint 0603M
footprint 0603L
footprint 0603_HV
footprint 0603S
pins: 1, 2

## RC0603FR-07182KL
designator R?  ValueDisplayed: 182k  (hidden comment: RC0603FR-07182KL)
RES, 182 k, 1%, 0.1 W, 0603; Manufacturer: Yageo America; CompType: Resistor; Value: 182k; Res_ohm: 182000; Tolerance_%: 1; Power_W: 0.1; Value2: 0.1W; VDC_V: 150; TempCo: 200 ppm/C; SizeArea_mm2: 1.28; SizeX_mm: 1.6; SizeY_mm: 0.8; EIA_Code: E96; U/M: EA; AEC Category: Q200; Green_Lifecycle: Active; Green_REACh: Passed
signal-integrity model Resistor
simulation model Resistor
footprint 0603
footprint 0603M
footprint 0603L
footprint 0603_HV
footprint 0603S
pins: 1, 2

## RC0603FR-07182RL
designator R?  ValueDisplayed: 182  (hidden comment: RC0603FR-07182RL)
RES, 182, 1%, 0.1 W, 0603; Manufacturer: Yageo America; CompType: Resistor; Value: 182; Value_Code: 182R; Tolerance_%: 1; Power_W: 0.1; Value2: 0.1W; VDC_V: 150; TempCo: 200 ppm/C; SizeArea_mm2: 1.28; SizeX_mm: 1.6; SizeY_mm: 0.8; EIA_Code: E96; U/M: EA; AEC Category: Q200
signal-integrity model Resistor
simulation model Resistor
footprint 0603
footprint 0603M
footprint 0603L
footprint 0603_HV
footprint 0603S
pins: 1, 2

## RC0603FR-07187KL
designator R?  ValueDisplayed: 187k  (hidden comment: RC0603FR-07187KL)
RES, 187 k, 1%, 0.1 W, 0603; Manufacturer: Yageo America; CompType: Resistor; Value: 187k; Res_ohm: 187000; Tolerance_%: 1; Power_W: 0.1; Value2: 0.1W; VDC_V: 150; TempCo: 200 ppm/C; SizeArea_mm2: 1.28; SizeX_mm: 1.6; SizeY_mm: 0.8; EIA_Code: E96; U/M: EA; AEC Category: Q200; Green_Lifecycle: Active; Green_REACh: Passed
signal-integrity model Resistor
simulation model Resistor
footprint 0603
footprint 0603M
footprint 0603L
footprint 0603_HV
footprint 0603S
pins: 1, 2

## RC0603FR-07187RL
designator R?  ValueDisplayed: 187  (hidden comment: RC0603FR-07187RL)
RES, 187, 1%, 0.1 W, 0603; Manufacturer: Yageo America; CompType: Resistor; Value: 187; Value_Code: 187R; Tolerance_%: 1; Power_W: 0.1; Value2: 0.1W; VDC_V: 150; TempCo: 200 ppm/C; SizeArea_mm2: 1.28; SizeX_mm: 1.6; SizeY_mm: 0.8; EIA_Code: E96; U/M: EA; AEC Category: Q200; Green_Lifecycle: Active; Green_REACh: Passed
signal-integrity model Resistor
simulation model Resistor
footprint 0603
footprint 0603M
footprint 0603L
footprint 0603_HV
footprint 0603S
pins: 1, 2

## RC0603FR-07191KL
designator R?  ValueDisplayed: 191k  (hidden comment: RC0603FR-07191KL)
RES, 191 k, 1%, 0.1 W, 0603; Manufacturer: Yageo America; CompType: Resistor; Value: 191k; Res_ohm: 191000; Tolerance_%: 1; Power_W: 0.1; Value2: 0.1W; VDC_V: 150; TempCo: 200 ppm/C; SizeArea_mm2: 1.28; SizeX_mm: 1.6; SizeY_mm: 0.8; EIA_Code: E96; U/M: EA; AEC Category: Q200
signal-integrity model Resistor
simulation model Resistor
footprint 0603
footprint 0603M
footprint 0603L
footprint 0603_HV
footprint 0603S
pins: 1, 2

## RC0603FR-07191RL
designator R?  ValueDisplayed: 191  (hidden comment: RC0603FR-07191RL)
RES, 191, 1%, 0.1 W, 0603; Manufacturer: Yageo America; CompType: Resistor; Value: 191; Value_Code: 191R; Tolerance_%: 1; Power_W: 0.1; Value2: 0.1W; VDC_V: 150; TempCo: 200 ppm/C; SizeArea_mm2: 1.28; SizeX_mm: 1.6; SizeY_mm: 0.8; EIA_Code: E96; U/M: EA; AEC Category: Q200
signal-integrity model Resistor
simulation model Resistor
footprint 0603
footprint 0603M
footprint 0603L
footprint 0603_HV
footprint 0603S
pins: 1, 2

## RC0603FR-07196KL
designator R?  ValueDisplayed: 196k  (hidden comment: RC0603FR-07196KL)
RES, 196 k, 1%, 0.1 W, 0603; Manufacturer: Yageo America; CompType: Resistor; Value: 196k; Res_ohm: 196000; Tolerance_%: 1; Power_W: 0.1; Value2: 0.1W; VDC_V: 150; TempCo: 200 ppm/C; SizeArea_mm2: 1.28; SizeX_mm: 1.6; SizeY_mm: 0.8; EIA_Code: E96; U/M: EA; AEC Category: Q200; Green_Lifecycle: Active; Green_REACh: Passed
signal-integrity model Resistor
simulation model Resistor
footprint 0603
footprint 0603M
footprint 0603L
footprint 0603_HV
footprint 0603S
pins: 1, 2

## RC0603FR-07196RL
designator R?  ValueDisplayed: 196  (hidden comment: RC0603FR-07196RL)
RES, 196, 1%, 0.1 W, 0603; Manufacturer: Yageo America; CompType: Resistor; Value: 196; Value_Code: 196R; Tolerance_%: 1; Power_W: 0.1; Value2: 0.1W; VDC_V: 150; TempCo: 200 ppm/C; SizeArea_mm2: 1.28; SizeX_mm: 1.6; SizeY_mm: 0.8; EIA_Code: E96; U/M: EA; AEC Category: Q200; Green_Lifecycle: Active; Green_REACh: Passed
signal-integrity model Resistor
simulation model Resistor
footprint 0603
footprint 0603M
footprint 0603L
footprint 0603_HV
footprint 0603S
pins: 1, 2

## RC0603FR-07200KL
designator R?  ValueDisplayed: 200k  (hidden comment: RC0603FR-07200KL)
RES, 200 k, 1%, 0.1 W, 0603; Manufacturer: Yageo America; CompType: Resistor; Value: 200k; Res_ohm: 200000; Tolerance_%: 1; Power_W: 0.1; Value2: 0.1W; VDC_V: 150; TempCo: 200 ppm/C; SizeArea_mm2: 1.28; SizeX_mm: 1.6; SizeY_mm: 0.8; EIA_Code: E96; U/M: EA; AEC Category: Q200; Green_Lifecycle: Active; Green_REACh: Passed
signal-integrity model Resistor
simulation model Resistor
footprint 0603
footprint 0603M
footprint 0603L
footprint 0603_HV
footprint 0603S
pins: 1, 2

## RC0603FR-07200RL
designator R?  ValueDisplayed: 200  (hidden comment: RC0603FR-07200RL)
RES, 200, 1%, 0.1 W, 0603; Manufacturer: Yageo America; CompType: Resistor; Value: 200; Value_Code: 200R; Tolerance_%: 1; Power_W: 0.1; Value2: 0.1W; VDC_V: 150; TempCo: 200 ppm/C; SizeArea_mm2: 1.28; SizeX_mm: 1.6; SizeY_mm: 0.8; EIA_Code: E96; U/M: EA; AEC Category: Q200; Green_Lifecycle: Active; Green_REACh: Passed
signal-integrity model Resistor
simulation model Resistor
footprint 0603
footprint 0603M
footprint 0603L
footprint 0603_HV
footprint 0603S
pins: 1, 2

## RC0603FR-07205KL
designator R?  ValueDisplayed: 205k  (hidden comment: RC0603FR-07205KL)
RES, 205 k, 1%, 0.1 W, 0603; Manufacturer: Yageo America; CompType: Resistor; Value: 205k; Res_ohm: 205000; Tolerance_%: 1; Power_W: 0.1; Value2: 0.1W; VDC_V: 150; TempCo: 200 ppm/C; SizeArea_mm2: 1.28; SizeX_mm: 1.6; SizeY_mm: 0.8; EIA_Code: E96; U/M: EA; AEC Category: Q200
signal-integrity model Resistor
simulation model Resistor
footprint 0603
footprint 0603M
footprint 0603L
footprint 0603_HV
footprint 0603S
pins: 1, 2

## RC0603FR-07205RL
designator R?  ValueDisplayed: 205  (hidden comment: RC0603FR-07205RL)
RES, 205, 1%, 0.1 W, 0603; Manufacturer: Yageo America; CompType: Resistor; Value: 205; Value_Code: 205R; Tolerance_%: 1; Power_W: 0.1; Value2: 0.1W; VDC_V: 150; TempCo: 200 ppm/C; SizeArea_mm2: 1.28; SizeX_mm: 1.6; SizeY_mm: 0.8; EIA_Code: E96; U/M: EA; AEC Category: Q200
signal-integrity model Resistor
simulation model Resistor
footprint 0603
footprint 0603M
footprint 0603L
footprint 0603_HV
footprint 0603S
pins: 1, 2

## RC0603FR-07210KL
designator R?  ValueDisplayed: 210k  (hidden comment: RC0603FR-07210KL)
RES, 210 k, 1%, 0.1 W, 0603; Manufacturer: Yageo America; CompType: Resistor; Value: 210k; Res_ohm: 210000; Tolerance_%: 1; Power_W: 0.1; Value2: 0.1W; VDC_V: 150; TempCo: 200 ppm/C; SizeArea_mm2: 1.28; SizeX_mm: 1.6; SizeY_mm: 0.8; EIA_Code: E96; U/M: EA; AEC Category: Q200
signal-integrity model Resistor
simulation model Resistor
footprint 0603
footprint 0603M
footprint 0603L
footprint 0603_HV
footprint 0603S
pins: 1, 2

## RC0603FR-07210RL
designator R?  ValueDisplayed: 210  (hidden comment: RC0603FR-07210RL)
RES, 210, 1%, 0.1 W, 0603; Manufacturer: Yageo America; CompType: Resistor; Value: 210; Value_Code: 210R; Tolerance_%: 1; Power_W: 0.1; Value2: 0.1W; VDC_V: 150; TempCo: 200 ppm/C; SizeArea_mm2: 1.28; SizeX_mm: 1.6; SizeY_mm: 0.8; EIA_Code: E96; U/M: EA; AEC Category: Q200
signal-integrity model Resistor
simulation model Resistor
footprint 0603
footprint 0603M
footprint 0603L
footprint 0603_HV
footprint 0603S
pins: 1, 2

## RC0603FR-07215KL
designator R?  ValueDisplayed: 215k  (hidden comment: RC0603FR-07215KL)
RES, 215 k, 1%, 0.1 W, 0603; Manufacturer: Yageo America; CompType: Resistor; Value: 215k; Res_ohm: 215000; Tolerance_%: 1; Power_W: 0.1; Value2: 0.1W; VDC_V: 150; TempCo: 200 ppm/C; SizeArea_mm2: 1.28; SizeX_mm: 1.6; SizeY_mm: 0.8; EIA_Code: E96; U/M: EA; AEC Category: Q200; Green_Lifecycle: Active; Green_REACh: Passed
signal-integrity model Resistor
simulation model Resistor
footprint 0603
footprint 0603M
footprint 0603L
footprint 0603_HV
footprint 0603S
pins: 1, 2

## RC0603FR-07215RL
designator R?  ValueDisplayed: 215  (hidden comment: RC0603FR-07215RL)
RES, 215, 1%, 0.1 W, 0603; Manufacturer: Yageo America; CompType: Resistor; Value: 215; Value_Code: 215R; Tolerance_%: 1; Power_W: 0.1; Value2: 0.1W; VDC_V: 150; TempCo: 200 ppm/C; SizeArea_mm2: 1.28; SizeX_mm: 1.6; SizeY_mm: 0.8; EIA_Code: E96; U/M: EA; AEC Category: Q200
signal-integrity model Resistor
simulation model Resistor
footprint 0603
footprint 0603M
footprint 0603L
footprint 0603_HV
footprint 0603S
pins: 1, 2

## RC0603FR-07220KL
designator R?  ValueDisplayed: 220k  (hidden comment: RC0603FR-07220KL)
RES, 220 k, 1%, 0.1 W, 0603; Manufacturer: Yageo America; CompType: Resistor; Value: 220k; Res_ohm: 220000; Tolerance_%: 1; Power_W: 0.1; Value2: 0.1W; VDC_V: 150; TempCo: 200 ppm/C; SizeArea_mm2: 1.28; SizeX_mm: 1.6; SizeY_mm: 0.8; U/M: EA; AEC Category: Q200; Green_Lifecycle: Active; Green_REACh: Passed
signal-integrity model Resistor
simulation model Resistor
footprint 0603
footprint 0603M
footprint 0603L
footprint 0603_HV
footprint 0603S
pins: 1, 2

## RC0603FR-07220RL
designator R?  ValueDisplayed: 220  (hidden comment: RC0603FR-07220RL)
RES, 220, 1%, 0.1 W, 0603; Manufacturer: Yageo America; CompType: Resistor; Value: 220; Value_Code: 220R; Tolerance_%: 1; Power_W: 0.1; Value2: 0.1W; VDC_V: 150; TempCo: 200 ppm/C; SizeArea_mm2: 1.28; SizeX_mm: 1.6; SizeY_mm: 0.8; U/M: EA; AEC Category: Q200; Green_Lifecycle: Active; Green_REACh: Passed
signal-integrity model Resistor
simulation model Resistor
footprint 0603
footprint 0603M
footprint 0603L
footprint 0603_HV
footprint 0603S
pins: 1, 2

## RC0603FR-07221KL
designator R?  ValueDisplayed: 221k  (hidden comment: RC0603FR-07221KL)
RES, 221 k, 1%, 0.1 W, 0603; Manufacturer: Yageo America; CompType: Resistor; Value: 221k; Res_ohm: 221000; Tolerance_%: 1; Power_W: 0.1; Value2: 0.1W; VDC_V: 150; TempCo: 200 ppm/C; SizeArea_mm2: 1.28; SizeX_mm: 1.6; SizeY_mm: 0.8; EIA_Code: E96; U/M: EA; AEC Category: Q200; Green_Lifecycle: Active; Green_REACh: Passed
signal-integrity model Resistor
simulation model Resistor
footprint 0603
footprint 0603M
footprint 0603L
footprint 0603_HV
footprint 0603S
pins: 1, 2

## RC0603FR-07221RL
designator R?  ValueDisplayed: 221  (hidden comment: RC0603FR-07221RL)
RES, 221, 1%, 0.1 W, 0603; Manufacturer: Yageo America; CompType: Resistor; Value: 221; Value_Code: 221R; Tolerance_%: 1; Power_W: 0.1; Value2: 0.1W; VDC_V: 150; TempCo: 200 ppm/C; SizeArea_mm2: 1.28; SizeX_mm: 1.6; SizeY_mm: 0.8; EIA_Code: E96; U/M: EA; AEC Category: Q200
signal-integrity model Resistor
simulation model Resistor
footprint 0603
footprint 0603M
footprint 0603L
footprint 0603_HV
footprint 0603S
pins: 1, 2

## RC0603FR-07226KL
designator R?  ValueDisplayed: 226k  (hidden comment: RC0603FR-07226KL)
RES, 226 k, 1%, 0.1 W, 0603; Manufacturer: Yageo America; CompType: Resistor; Value: 226k; Res_ohm: 226000; Tolerance_%: 1; Power_W: 0.1; Value2: 0.1W; VDC_V: 150; TempCo: 200 ppm/C; SizeArea_mm2: 1.28; SizeX_mm: 1.6; SizeY_mm: 0.8; EIA_Code: E96; U/M: EA; AEC Category: Q200
signal-integrity model Resistor
simulation model Resistor
footprint 0603
footprint 0603M
footprint 0603L
footprint 0603_HV
footprint 0603S
pins: 1, 2

## RC0603FR-07226RL
designator R?  ValueDisplayed: 226  (hidden comment: RC0603FR-07226RL)
RES, 226, 1%, 0.1 W, 0603; Manufacturer: Yageo America; CompType: Resistor; Value: 226; Value_Code: 226R; Tolerance_%: 1; Power_W: 0.1; Value2: 0.1W; VDC_V: 150; TempCo: 200 ppm/C; SizeArea_mm2: 1.28; SizeX_mm: 1.6; SizeY_mm: 0.8; EIA_Code: E96; U/M: EA; AEC Category: Q200
signal-integrity model Resistor
simulation model Resistor
footprint 0603
footprint 0603M
footprint 0603L
footprint 0603_HV
footprint 0603S
pins: 1, 2

## RC0603FR-07232KL
designator R?  ValueDisplayed: 232k  (hidden comment: RC0603FR-07232KL)
RES, 232 k, 1%, 0.1 W, 0603; Manufacturer: Yageo America; CompType: Resistor; Value: 232k; Res_ohm: 232000; Tolerance_%: 1; Power_W: 0.1; Value2: 0.1W; VDC_V: 150; TempCo: 200 ppm/C; SizeArea_mm2: 1.28; SizeX_mm: 1.6; SizeY_mm: 0.8; EIA_Code: E96; U/M: EA; AEC Category: Q200; Green_Lifecycle: Active; Green_REACh: Passed
signal-integrity model Resistor
simulation model Resistor
footprint 0603
footprint 0603M
footprint 0603L
footprint 0603_HV
footprint 0603S
pins: 1, 2

## RC0603FR-07232RL
designator R?  ValueDisplayed: 232  (hidden comment: RC0603FR-07232RL)
RES, 232, 1%, 0.1 W, 0603; Manufacturer: Yageo America; CompType: Resistor; Value: 232; Value_Code: 232R; Tolerance_%: 1; Power_W: 0.1; Value2: 0.1W; VDC_V: 150; TempCo: 200 ppm/C; SizeArea_mm2: 1.28; SizeX_mm: 1.6; SizeY_mm: 0.8; EIA_Code: E96; U/M: EA; AEC Category: Q200
signal-integrity model Resistor
simulation model Resistor
footprint 0603
footprint 0603M
footprint 0603L
footprint 0603_HV
footprint 0603S
pins: 1, 2

## RC0603FR-07237KL
designator R?  ValueDisplayed: 237k  (hidden comment: RC0603FR-07237KL)
RES, 237 k, 1%, 0.1 W, 0603; Manufacturer: Yageo America; CompType: Resistor; Value: 237k; Res_ohm: 237000; Tolerance_%: 1; Power_W: 0.1; Value2: 0.1W; VDC_V: 150; TempCo: 200 ppm/C; SizeArea_mm2: 1.28; SizeX_mm: 1.6; SizeY_mm: 0.8; EIA_Code: E96; U/M: EA; AEC Category: Q200; Green_Lifecycle: Active; Green_REACh: Passed
signal-integrity model Resistor
simulation model Resistor
footprint 0603
footprint 0603M
footprint 0603L
footprint 0603_HV
footprint 0603S
pins: 1, 2

## RC0603FR-07237RL
designator R?  ValueDisplayed: 237  (hidden comment: RC0603FR-07237RL)
RES, 237, 1%, 0.1 W, 0603; Manufacturer: Yageo America; CompType: Resistor; Value: 237; Value_Code: 237R; Tolerance_%: 1; Power_W: 0.1; Value2: 0.1W; VDC_V: 150; TempCo: 200 ppm/C; SizeArea_mm2: 1.28; SizeX_mm: 1.6; SizeY_mm: 0.8; EIA_Code: E96; U/M: EA; AEC Category: Q200
signal-integrity model Resistor
simulation model Resistor
footprint 0603
footprint 0603M
footprint 0603L
footprint 0603_HV
footprint 0603S
pins: 1, 2

## RC0603FR-07240KL
designator R?  ValueDisplayed: 240k  (hidden comment: RC0603FR-07240KL)
RES, 240 k, 1%, 0.1 W, 0603; Manufacturer: Yageo America; CompType: Resistor; Value: 240k; Res_ohm: 240000; Tolerance_%: 1; Power_W: 0.1; Value2: 0.1W; VDC_V: 150; TempCo: 200 ppm/C; SizeArea_mm2: 1.28; SizeX_mm: 1.6; SizeY_mm: 0.8; U/M: EA; AEC Category: Q200; Green_Lifecycle: Active; Green_REACh: Passed
signal-integrity model Resistor
simulation model Resistor
footprint 0603
footprint 0603M
footprint 0603L
footprint 0603_HV
footprint 0603S
pins: 1, 2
